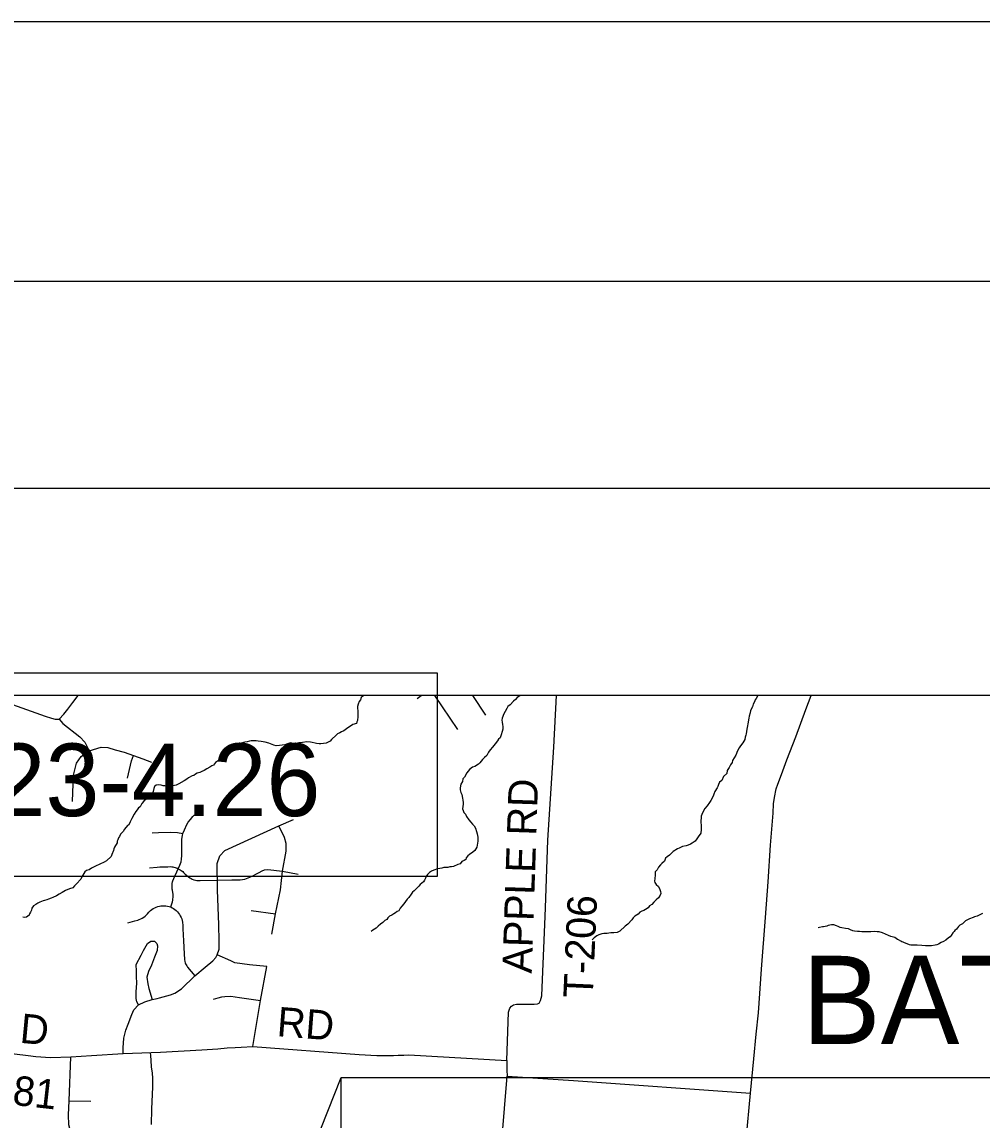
# Model space of a CAD drawing. Extents: x 0 to 39.3, y -3.9 to 22.
# Drawn here: x 4.246 to 6.099, y 19.881 to 22 of the extents above; entities that cross this region are included whole.
import ezdxf

# ---------------------------------------------------------------- set-up
doc = ezdxf.new("R2010")
doc.units = 0
for name, color, linetype in [('GM_X_Corporation', 7, 'Continuous'), ('GM_X_County_Road', 7, 'Continuous'), ('GM_X_Minor_River', 7, 'Continuous'), ('GM_X_State_Route', 7, 'Continuous'), ('GM_X_Township_Road', 7, 'Continuous'), ('GM_X_Township_Road_Text', 7, 'Continuous'), ('GM_X_Township_Text', 7, 'Continuous'), ('SH_Border', 7, 'Continuous'), ('SH_Cut_Line', 7, 'Continuous'), ('SH_Data', 7, 'Continuous'), ('SH_Text', 7, 'Continuous')]:
    doc.layers.add(name, color=color, linetype=linetype)

msp = doc.modelspace()

# ---------------------------------------------------------------- linework, layer by layer
at = {"layer": 'GM_X_Corporation'}
msp.add_lwpolyline([(8.7, 20.7), (3.278, 20.7), (3.1219, 20.3298), (3.0652, 20.1955), (2.9744, 19.9801), (2.9689, 19.967), (2.8945, 19.7907)], dxfattribs=at)
at = {"layer": 'GM_X_County_Road'}
msp.add_lwpolyline([(4.1805, 20.7), (4.1977, 20.6933), (4.2272, 20.683), (4.2905, 20.6603), (4.3025, 20.6564), (4.3097, 20.6547), (4.3175, 20.6542), (4.3266, 20.6644), (4.3343, 20.6739), (4.3441, 20.6868), (4.3539, 20.7)], dxfattribs=at)
at = {"layer": 'GM_X_Minor_River'}
for points in [[(4.9062, 20.7), (4.9039, 20.6991), (4.9004, 20.6961), (4.8992, 20.6919), (4.8965, 20.6885), (4.8945, 20.6833), (4.8936, 20.6787), (4.8936, 20.6749), (4.8939, 20.6711), (4.8942, 20.665), (4.8941, 20.6597), (4.8932, 20.6521), (4.8924, 20.6491), (4.8912, 20.6461), (4.8847, 20.6439), (4.8816, 20.6424), (4.8747, 20.638), (4.867, 20.632), (4.8624, 20.6302), (4.859, 20.6284), (4.8551, 20.6262), (4.852, 20.6236), (4.8435, 20.6154), (4.8404, 20.612), (4.837, 20.6101), (4.8331, 20.6083), (4.8278, 20.6073), (4.8229, 20.6066), (4.8194, 20.6067), (4.8145, 20.6075), (4.8115, 20.6079)], [(5.2076, 20.7), (5.2069, 20.6998), (5.2019, 20.6965), (5.1984, 20.6924), (5.1945, 20.689), (5.188, 20.6823), (5.1837, 20.6789), (5.1814, 20.6748), (5.1782, 20.6695), (5.1751, 20.6635), (5.1739, 20.6597), (5.1727, 20.6567), (5.1722, 20.6525), (5.1726, 20.6487), (5.1736, 20.6442), (5.1739, 20.6403), (5.1739, 20.635), (5.1726, 20.6309), (5.171, 20.6241), (5.169, 20.6184), (5.1655, 20.6158), (5.164, 20.6128), (5.1589, 20.6068), (5.1539, 20.6004), (5.1496, 20.5955), (5.1461, 20.5907), (5.143, 20.5846), (5.1383, 20.5805), (5.1349, 20.5764), (5.1298, 20.5704), (5.1267, 20.5674), (5.1198, 20.563), (5.1152, 20.5616), (5.1094, 20.5571), (5.1048, 20.5511), (5.1001, 20.5424), (5.0966, 20.5395), (5.0961, 20.5341), (5.093, 20.5293), (5.0917, 20.5217), (5.0917, 20.5183), (5.0927, 20.5129), (5.0949, 20.5091), (5.0963, 20.5018), (5.097, 20.498), (5.0973, 20.4938), (5.0973, 20.4904), (5.0968, 20.4862), (5.0964, 20.4817), (5.0971, 20.4779), (5.0989, 20.4744), (5.1019, 20.4709), (5.1041, 20.4667), (5.1086, 20.4602), (5.1123, 20.4555), (5.1157, 20.4517), (5.1186, 20.4486), (5.1209, 20.4444), (5.1234, 20.4375), (5.1245, 20.4333), (5.1252, 20.4302), (5.1259, 20.4268)], [(5.6662, 20.7), (5.663, 20.6945), (5.661, 20.6915), (5.6598, 20.6877), (5.6575, 20.6832), (5.6559, 20.6783), (5.6523, 20.6715), (5.6515, 20.6666), (5.6495, 20.6605), (5.6487, 20.6563), (5.647, 20.6454), (5.6465, 20.6416), (5.6453, 20.6351), (5.644, 20.6264), (5.6432, 20.6234), (5.642, 20.6196), (5.6411, 20.6154), (5.6376, 20.609), (5.6329, 20.603), (5.6302, 20.5989), (5.6271, 20.5936), (5.6235, 20.5849), (5.6176, 20.5748), (5.6168, 20.571), (5.6133, 20.5665), (5.611, 20.5612), (5.6074, 20.5552), (5.6066, 20.5499), (5.6, 20.5435), (5.5965, 20.536), (5.5922, 20.5326), (5.5903, 20.5281), (5.5891, 20.5247), (5.5875, 20.5217), (5.5832, 20.5149), (5.5812, 20.5097), (5.58, 20.5059), (5.5757, 20.4976), (5.5729, 20.4935), (5.5683, 20.4871), (5.564, 20.4822), (5.5597, 20.4739), (5.5569, 20.4675), (5.5569, 20.4641), (5.556, 20.4584), (5.5566, 20.447), (5.5572, 20.4413), (5.556, 20.4344), (5.5509, 20.4277), (5.5486, 20.4236), (5.5455, 20.4187), (5.5397, 20.415), (5.5362, 20.4131), (5.532, 20.4113), (5.5278, 20.4102), (5.521, 20.4085), (5.5144, 20.4055), (5.5114, 20.4041), (5.5029, 20.3989), (5.4956, 20.3918), (5.4914, 20.3888), (5.4883, 20.3862), (5.4863, 20.3806), (5.4809, 20.3761), (5.4782, 20.3731), (5.4743, 20.3686), (5.4719, 20.3637), (5.4684, 20.3596), (5.4683, 20.3535), (5.4675, 20.3467), (5.467, 20.3421), (5.4677, 20.3391), (5.4699, 20.3356)], [(4.8115, 20.6079), (4.8062, 20.6095), (4.8028, 20.6104), (4.7959, 20.6105), (4.7875, 20.6095), (4.7799, 20.6085), (4.7731, 20.6071), (4.7696, 20.6075), (4.7666, 20.608), (4.7636, 20.6088), (4.7605, 20.6077), (4.7563, 20.6062), (4.7529, 20.6052), (4.7426, 20.6034), (4.7365, 20.6032), (4.7319, 20.604), (4.7289, 20.6056), (4.7255, 20.6068), (4.7225, 20.608), (4.7153, 20.61), (4.7077, 20.6113), (4.7017, 20.6121), (4.6975, 20.6126), (4.688, 20.6128), (4.6846, 20.6117), (4.6807, 20.6106), (4.6762, 20.6099), (4.6731, 20.6096), (4.667, 20.6078), (4.6628, 20.6048), (4.6566, 20.6), (4.6516, 20.5978), (4.647, 20.5941), (4.6431, 20.5911), (4.6389, 20.5885), (4.6339, 20.5841), (4.6304, 20.5811), (4.6262, 20.577), (4.6231, 20.5732), (4.6192, 20.571), (4.6154, 20.5658), (4.6123, 20.5643), (4.6081, 20.5621), (4.6023, 20.5584), (4.5973, 20.5554), (4.5927, 20.5536), (4.5889, 20.5518), (4.5839, 20.55), (4.5805, 20.5481), (4.5774, 20.5459), (4.5743, 20.5448), (4.5674, 20.5411), (4.564, 20.5385), (4.5586, 20.5352), (4.5482, 20.5297), (4.5432, 20.5271), (4.5402, 20.5264), (4.5371, 20.5261), (4.5337, 20.5261), (4.5307, 20.5258), (4.5276, 20.5251), (4.5246, 20.5252), (4.5215, 20.5256), (4.5181, 20.526), (4.5143, 20.5269), (4.509, 20.5277), (4.5048, 20.527), (4.5014, 20.5248), (4.5005, 20.5206), (4.4989, 20.5146), (4.4965, 20.5067), (4.4923, 20.5029), (4.4888, 20.5019), (4.4854, 20.5), (4.4811, 20.4963), (4.4772, 20.4914), (4.4737, 20.485), (4.4706, 20.4832), (4.4679, 20.4798), (4.4652, 20.476), (4.4625, 20.4711), (4.4578, 20.4629), (4.4542, 20.4561), (4.4522, 20.4508), (4.4492, 20.449), (4.4468, 20.446), (4.4429, 20.4415), (4.4414, 20.4384), (4.436, 20.4325), (4.4336, 20.4283), (4.432, 20.4253), (4.4308, 20.4219), (4.4296, 20.4189), (4.4292, 20.4155), (4.4245, 20.4072), (4.4233, 20.4042), (4.4225, 20.4008), (4.419, 20.3936), (4.4181, 20.3894), (4.4085, 20.3812), (4.4046, 20.3787)], [(5.1259, 20.4268), (5.1254, 20.4192), (5.1249, 20.415), (5.1245, 20.4116), (5.1237, 20.4075), (5.1201, 20.4007), (5.1163, 20.3981), (5.1097, 20.3933), (5.1066, 20.3906), (5.1032, 20.3869), (5.1027, 20.3839), (5.0993, 20.3817), (5.0951, 20.3798), (5.0919, 20.3753), (5.0874, 20.3743), (5.0789, 20.3702), (5.0747, 20.3695), (5.0717, 20.3692), (5.0675, 20.3685), (5.0637, 20.3682), (5.0603, 20.3679), (5.0561, 20.3672), (5.0526, 20.3665), (5.0481, 20.3654), (5.0408, 20.3633), (5.0362, 20.3611), (5.0327, 20.3585), (5.0285, 20.3548), (5.0261, 20.3506), (5.0246, 20.3476), (5.023, 20.3438), (5.0206, 20.3408), (5.0176, 20.3378), (5.0145, 20.3352), (5.0118, 20.3319), (5.0075, 20.3274), (5.0025, 20.3233), (4.9994, 20.3203), (4.9967, 20.3166), (4.9924, 20.3105), (4.9893, 20.3068), (4.9827, 20.2982), (4.9788, 20.2937), (4.9757, 20.2895), (4.9729, 20.2843), (4.9699, 20.2832), (4.9668, 20.281), (4.9637, 20.2787), (4.9595, 20.2761), (4.9553, 20.2743), (4.9522, 20.2713), (4.9502, 20.2679), (4.9464, 20.2657), (4.9425, 20.262), (4.9379, 20.2587), (4.9333, 20.2549), (4.9294, 20.2512), (4.9263, 20.249), (4.9233, 20.2471), (4.9198, 20.2449)], [(4.4046, 20.3787), (4.3962, 20.3746), (4.3878, 20.371), (4.3836, 20.3688), (4.3801, 20.3669), (4.3755, 20.3636), (4.3705, 20.3622), (4.3671, 20.3599), (4.3632, 20.3535), (4.3604, 20.3486), (4.3592, 20.3456), (4.3511, 20.3366), (4.3468, 20.3329), (4.3437, 20.3292), (4.3376, 20.327), (4.3296, 20.3237), (4.3234, 20.32), (4.3177, 20.3167), (4.3123, 20.3134), (4.3054, 20.3101), (4.3023, 20.309), (4.2966, 20.3068), (4.2936, 20.3061), (4.2893, 20.3043), (4.2863, 20.3036), (4.2802, 20.301), (4.2763, 20.2992), (4.2721, 20.297), (4.2679, 20.2944), (4.2648, 20.2895), (4.2639, 20.2861), (4.2624, 20.2823), (4.2604, 20.2789), (4.2592, 20.2759), (4.2546, 20.2726), (4.2512, 20.2715), (4.2474, 20.2723)], [(5.4699, 20.3356), (5.4744, 20.3313), (5.477, 20.326), (5.4784, 20.3218), (5.4788, 20.3183), (5.4776, 20.3146), (5.4744, 20.3097), (5.4702, 20.3059), (5.4656, 20.3015), (5.4617, 20.2966), (5.4574, 20.294), (5.4543, 20.2906), (5.4497, 20.2869), (5.4463, 20.2855), (5.4424, 20.284), (5.4386, 20.2822), (5.4351, 20.278), (5.429, 20.2744), (5.4259, 20.271), (5.4228, 20.2669), (5.4154, 20.259), (5.4104, 20.2549), (5.4, 20.2452), (5.3946, 20.2426), (5.3885, 20.242), (5.3824, 20.2421), (5.3786, 20.2414), (5.3752, 20.2411), (5.3722, 20.2411), (5.3687, 20.2408), (5.3649, 20.2401), (5.3592, 20.2383), (5.3557, 20.2365), (5.3503, 20.2324), (5.3465, 20.2283)], [(6.1001, 20.2793), (6.0959, 20.2778), (6.0897, 20.2745), (6.0844, 20.2731), (6.0817, 20.272), (6.0748, 20.2691), (6.0721, 20.2676), (6.0671, 20.265), (6.0613, 20.2598), (6.0564, 20.2572), (6.054, 20.2546), (6.0498, 20.2494), (6.0467, 20.2468), (6.0451, 20.2445), (6.0428, 20.2419), (6.0397, 20.237), (6.0373, 20.2344), (6.0343, 20.2322), (6.0293, 20.2277), (6.0247, 20.2255), (6.0204, 20.2233), (6.0151, 20.22), (6.012, 20.2189), (6.0086, 20.2182), (6.0013, 20.2172), (5.9956, 20.2169), (5.993, 20.2169), (5.9903, 20.217), (5.9827, 20.2175), (5.974, 20.218), (5.9652, 20.2182), (5.9618, 20.2186), (5.9588, 20.2187), (5.9546, 20.221), (5.9493, 20.223), (5.9467, 20.2242), (5.9444, 20.225), (5.9422, 20.2262), (5.938, 20.2285), (5.9358, 20.2293), (5.9309, 20.2328), (5.9233, 20.2353), (5.9184, 20.2372), (5.9127, 20.2396), (5.9071, 20.2424), (5.9003, 20.244), (5.8965, 20.2441), (5.8912, 20.2446), (5.8847, 20.2443), (5.8797, 20.244), (5.8668, 20.2442), (5.8626, 20.2447), (5.8585, 20.2448), (5.8532, 20.2456), (5.8497, 20.246), (5.8452, 20.248), (5.8414, 20.2496), (5.8357, 20.2505), (5.8285, 20.2517), (5.8255, 20.2522), (5.8217, 20.2545), (5.8183, 20.2557), (5.8131, 20.2573), (5.8108, 20.2578), (5.8085, 20.2574), (5.802, 20.256)], [(5.802, 20.256), (5.7993, 20.2553), (5.7963, 20.2546), (5.7932, 20.2539), (5.7909, 20.2539), (5.7856, 20.2521), (5.7825, 20.2518)]]:
    msp.add_lwpolyline(points, dxfattribs=at)
at = {"layer": 'GM_X_State_Route'}
for points in [[(5.702, 20.5198), (5.705, 20.5291), (5.7121, 20.548), (5.7224, 20.576), (5.7395, 20.6202), (5.7592, 20.6729), (5.769, 20.7)], [(5.6327, 19.7252), (5.6337, 19.7332), (5.6393, 19.7899), (5.6439, 19.8424), (5.6523, 19.9327), (5.6583, 19.9989), (5.663, 20.0465), (5.6674, 20.0875), (5.6736, 20.1721), (5.6813, 20.2714), (5.6861, 20.3405), (5.6907, 20.411), (5.6956, 20.4732), (5.6968, 20.4908), (5.6985, 20.5034), (5.702, 20.5198)]]:
    msp.add_lwpolyline(points, dxfattribs=at)
at = {"layer": 'GM_X_Township_Road'}
for p, q in [((5.0086, 20.6946), (5.0166, 20.7)), ((5.0421, 20.7), (5.0863, 20.6345)), ((5.1152, 20.7), (5.1405, 20.6625)), ((5.2562, 20.2906), (5.261, 20.4208)), ((4.6883, 20.2852), (4.7352, 20.279)), ((4.337, 19.918), (4.3786, 19.9172))]:
    msp.add_line(p, q, dxfattribs=at)
for points in [[(5.261, 20.4208), (5.2726, 20.6002), (5.2776, 20.7)], [(4.3175, 20.6542), (4.3244, 20.6463), (4.3576, 20.6206), (4.3671, 20.6098), (4.3751, 20.5931)], [(4.3429, 20.4957), (4.3449, 20.5465), (4.3506, 20.5698), (4.3597, 20.5825), (4.3751, 20.5931), (4.3986, 20.6007), (4.4111, 20.5998), (4.4255, 20.5955), (4.4432, 20.5908), (4.4608, 20.5841), (4.4787, 20.5776), (4.4959, 20.5718)], [(4.4495, 20.5403), (4.4571, 20.5738), (4.4608, 20.5841)], [(4.5328, 20.292), (4.536, 20.3022), (4.5367, 20.3051), (4.5372, 20.3077), (4.5376, 20.3106), (4.5378, 20.3127), (4.5378, 20.3144), (4.5376, 20.3168), (4.5371, 20.3197), (4.5362, 20.3243), (4.5358, 20.3264), (4.5354, 20.3294), (4.5353, 20.3316), (4.5353, 20.3345), (4.5356, 20.3374), (4.5363, 20.3405), (4.5371, 20.3426), (4.5388, 20.3471), (4.5473, 20.3657), (4.5507, 20.373), (4.5528, 20.3789), (4.5539, 20.3846), (4.5545, 20.3915), (4.5545, 20.401), (4.5542, 20.4102), (4.5542, 20.4168), (4.5545, 20.4228), (4.5555, 20.4298), (4.5565, 20.434), (4.5591, 20.4411), (4.5637, 20.4511), (4.5662, 20.4554), (4.5708, 20.4611), (4.5754, 20.4665), (4.5818, 20.4724), (4.5926, 20.4809)], [(4.5064, 20.1156), (4.5111, 20.1165), (4.5326, 20.1227), (4.541, 20.1258), (4.5534, 20.1338), (4.5793, 20.1589), (4.5993, 20.1757), (4.6142, 20.1883), (4.6196, 20.1946), (4.6224, 20.1998), (4.6261, 20.2106), (4.6263, 20.2266), (4.6255, 20.2573), (4.6234, 20.3253), (4.6228, 20.3437), (4.6224, 20.3595), (4.6223, 20.3762), (4.6274, 20.3907), (4.6371, 20.4011), (4.7414, 20.4489), (4.7697, 20.461)], [(4.497, 20.4354), (4.5094, 20.4355), (4.5317, 20.4362), (4.5459, 20.4358), (4.5565, 20.434)], [(4.7279, 20.2395), (4.7352, 20.279), (4.7445, 20.3248), (4.7483, 20.361), (4.7554, 20.3999), (4.756, 20.4145), (4.7526, 20.4259), (4.7414, 20.4489)], [(4.4918, 20.3675), (4.5068, 20.3689), (4.5116, 20.3693), (4.5161, 20.3694), (4.5218, 20.3696), (4.5273, 20.3698), (4.5321, 20.3699), (4.5347, 20.3698), (4.5367, 20.3695), (4.5386, 20.3691), (4.5415, 20.3682), (4.5451, 20.3667), (4.5473, 20.3657), (4.5512, 20.3635), (4.5532, 20.3622), (4.5559, 20.3602), (4.5574, 20.3587), (4.5589, 20.3573), (4.561, 20.3554), (4.5633, 20.3531), (4.5652, 20.3515), (4.5672, 20.35), (4.5697, 20.3483), (4.5722, 20.3468), (4.5745, 20.3457), (4.5774, 20.3447), (4.5805, 20.3439), (4.5833, 20.3434), (4.5899, 20.3431), (4.622, 20.3437), (4.6228, 20.3437), (4.6509, 20.3444), (4.667, 20.3443), (4.676, 20.346), (4.6857, 20.3493), (4.6925, 20.3526), (4.697, 20.3553), (4.7035, 20.3586), (4.7093, 20.3615), (4.7139, 20.3634), (4.7203, 20.3644), (4.7483, 20.361), (4.7791, 20.3554)], [(4.4499, 20.2613), (4.4636, 20.265), (4.4691, 20.2667), (4.4722, 20.2678), (4.4752, 20.269), (4.478, 20.2705), (4.4807, 20.2723), (4.4833, 20.2743), (4.4857, 20.2764), (4.4879, 20.2788), (4.4907, 20.2822), (4.4916, 20.2832), (4.4939, 20.2853), (4.4965, 20.2873), (4.4991, 20.2891), (4.5019, 20.2906), (4.5048, 20.2919), (4.5078, 20.2929), (4.5109, 20.2937), (4.514, 20.2942), (4.5172, 20.2945), (4.5204, 20.2945), (4.5236, 20.2943), (4.5267, 20.2938), (4.5298, 20.293), (4.5328, 20.292), (4.5357, 20.2905), (4.5384, 20.2889), (4.541, 20.287), (4.5435, 20.2849), (4.5457, 20.2826), (4.5478, 20.2802), (4.5497, 20.2776), (4.5513, 20.2748), (4.5527, 20.272), (4.554, 20.269), (4.5549, 20.2659), (4.5556, 20.2628), (4.5562, 20.2565), (4.5565, 20.2499), (4.5575, 20.2268), (4.5585, 20.2018), (4.5594, 20.1906), (4.56, 20.1866), (4.5606, 20.1843), (4.5615, 20.1821), (4.5624, 20.1803), (4.5636, 20.1785), (4.5654, 20.1761), (4.5793, 20.1589)], [(5.1817, 19.9958), (5.1851, 20.0888), (5.1875, 20.0967), (5.1907, 20.1008), (5.1945, 20.1033), (5.2002, 20.1043), (5.2343, 20.1046), (5.2412, 20.1048), (5.2442, 20.1066), (5.247, 20.1118), (5.2492, 20.1205), (5.2499, 20.1364), (5.255, 20.2581), (5.2562, 20.2906)], [(4.4707, 20.1031), (4.4672, 20.1087), (4.4663, 20.1153), (4.4663, 20.1281), (4.4672, 20.1451), (4.467, 20.1576), (4.4666, 20.1683), (4.4661, 20.1807), (4.4759, 20.1987), (4.4805, 20.2083), (4.4879, 20.2217), (4.4947, 20.2262), (4.5013, 20.226), (4.5058, 20.2215), (4.5072, 20.2172), (4.5066, 20.2083), (4.5016, 20.1954), (4.4959, 20.18), (4.49, 20.1672), (4.4866, 20.1566), (4.4883, 20.1435), (4.4907, 20.1344), (4.497, 20.1137)], [(4.6914, 20.0227), (4.7064, 20.1114), (4.7182, 20.1774), (4.6852, 20.1801), (4.6568, 20.1844), (4.6491, 20.1879), (4.6224, 20.1998)], [(4.4413, 20.0094), (4.4411, 20.0201), (4.4422, 20.0386), (4.4461, 20.0544), (4.4509, 20.0659), (4.4576, 20.0844), (4.4616, 20.0935), (4.4707, 20.1031), (4.4828, 20.1088), (4.497, 20.1137), (4.5064, 20.1156)], [(4.6154, 20.1138), (4.6247, 20.1166), (4.6313, 20.1187), (4.6371, 20.1194), (4.6486, 20.1196), (4.6658, 20.117), (4.7064, 20.1114)], [(4.0563, 20.0275), (4.2312, 20.0085), (4.2575, 20.0054), (4.2727, 20.0037), (4.3006, 20.0016), (4.3399, 20.0025), (4.3798, 20.0052), (4.4413, 20.0094), (4.5131, 20.0121), (4.5928, 20.0166), (4.6237, 20.0184), (4.6415, 20.0199), (4.6571, 20.021), (4.6689, 20.0214), (4.6914, 20.0227), (4.8963, 20.0073), (4.9305, 20.0051), (4.9446, 20.0051), (4.9626, 20.0057), (4.9722, 20.0062), (4.9826, 20.0062), (4.9926, 20.0068), (5.1817, 19.9958)], [(4.4954, 19.8721), (4.4963, 19.9017), (4.4981, 19.9448), (4.4985, 19.9613), (4.4977, 19.9721), (4.4959, 19.9828), (4.495, 19.9965), (4.4945, 20.0045), (4.4939, 20.0114)], [(4.318, 19.6326), (4.3589, 19.6327), (4.3709, 19.6334), (4.3773, 19.6365), (4.3805, 19.6416), (4.3831, 19.6509), (4.384, 19.6641), (4.3843, 19.7172), (4.3865, 19.7743), (4.3858, 19.7844), (4.3843, 19.7928), (4.3747, 19.8073), (4.3595, 19.827), (4.3483, 19.8404), (4.3405, 19.854), (4.3359, 19.8718), (4.3356, 19.8906), (4.337, 19.918), (4.3399, 20.0025)], [(5.1817, 19.9958), (5.1818, 19.9773), (5.1824, 19.9658)], [(5.1718, 19.8408), (5.1824, 19.9658)], [(5.1824, 19.9658), (5.3103, 19.9569), (5.6523, 19.9327)]]:
    msp.add_lwpolyline(points, dxfattribs=at)
at = {"layer": 'SH_Border'}
msp.add_lwpolyline([(1.5, 21.5), (33.5, 21.5), (33.5, 0.5), (1.5, 0.5)], close=True, dxfattribs=at)
at = {"layer": 'SH_Cut_Line'}
msp.add_lwpolyline([(0, 0), (34, 0), (34, 22), (0, 22)], close=True, dxfattribs=at)
at = {"layer": 'SH_Data'}
msp.add_lwpolyline([(1.9, 21.1), (9.1, 21.1), (9.1, 13.9), (1.9, 13.9)], close=True, dxfattribs=at)
at = {"layer": 'SH_Text'}
msp.add_line((4.2977, 18.5414), (4.8619, 19.963), dxfattribs=at)
for points in [[(3.5607, 20.744), (5.0473, 20.744), (5.0473, 20.3507), (3.5607, 20.3507)], [(4.8619, 19.963), (6.1914, 19.963), (6.1914, 19.5697), (4.8619, 19.5697)]]:
    msp.add_lwpolyline(points, close=True, dxfattribs=at)

# ---------------------------------------------------------------- texts
at = {"layer": 'GM_X_Township_Road_Text'}
for s, height, rotation, p in [('APPLE RD', 0.05682, 88.105, (5.2298, 20.1631)), ('T-206', 0.05682, 87.474, (5.3474, 20.1155)), ('RD', 0.05682, 355.5641, (4.7365, 20.0428)), ('D', 0.0568, 354.6233, (4.2401, 20.0301)), ('T-181', 0.05682, 353.5488, (4.1125, 19.9234))]:
    msp.add_text(s, height=height, rotation=rotation, dxfattribs=at).set_placement(p)
at = {"layer": 'GM_X_Township_Text'}
msp.add_text('BATAVIA', height=0.17045, rotation=0, dxfattribs=at).set_placement((5.7515, 20.0273))
at = {"layer": 'SH_Text'}
msp.add_text('SLM 4.23-4.26', height=0.14, dxfattribs=at).set_placement((3.5938, 20.4674))

doc.saveas('drawing.dxf')
